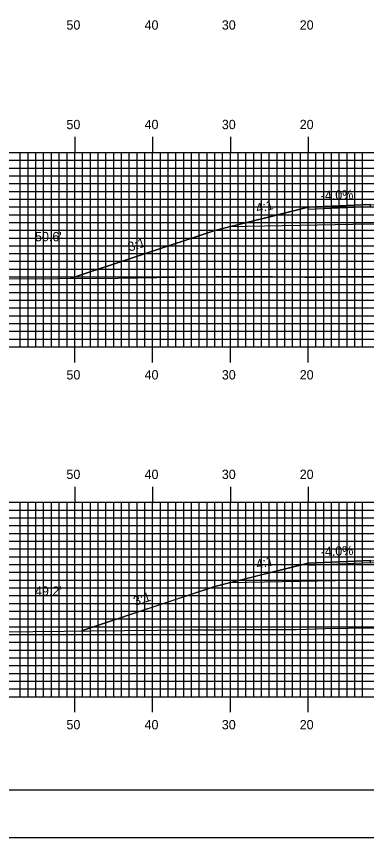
# Model space of a CAD drawing. Extents: x 1765333 to 1765676, y 442591 to 442811.
# Drawn here: x 1765440.9 to 1765485.9, y 442590.5 to 442696.2 of the extents above; entities that cross this region are included whole.
import ezdxf

# ---------------------------------------------------------------- set-up
doc = ezdxf.new("R2010")
doc.units = 0
for name, color, linetype in [('ANNOTATION', 7, 'Continuous'), ('BORDER', 7, 'Continuous'), ('D_Roadway_Centerline', 7, 'Continuous'), ('D_Roadway_Edge_Shoulder', 7, 'Continuous'), ('D_Roadway_SlopeLines', 7, 'Continuous'), ('D_Roadway_SubGrade', 7, 'Continuous'), ('D_Text_Standard', 7, 'Continuous'), ('H_V ANNOTATION', 7, 'Continuous'), ('MAJOR', 7, 'Continuous'), ('MINOR', 7, 'Continuous'), ('PLOT BOUNDARY', 7, 'Continuous'), ('S_Roadway_Centerline', 7, 'Continuous')]:
    doc.layers.add(name, color=color, linetype=linetype)

msp = doc.modelspace()

# ---------------------------------------------------------------- linework, layer by layer
at = {"layer": 'BORDER'}
msp.add_lwpolyline([(1765348.77, 442596.67), (1765668.77, 442596.67), (1765668.77, 442806.67), (1765348.77, 442806.67)], close=True, dxfattribs=at)
at = {"layer": 'D_Roadway_Centerline'}
for points in [[(1765447.79, 442662.46), (1765466.37, 442668.65), (1765466.37, 442668.65), (1765466.86, 442668.77), (1765468.2, 442669.11), (1765468.2, 442669.11), (1765473.59, 442670.45), (1765478.37, 442671.65), (1765478.37, 442671.65), (1765486.37, 442671.97), (1765486.38, 442671.97), (1765498.37, 442671.71), (1765510.37, 442671.44), (1765518.37, 442671.12), (1765518.37, 442671.12), (1765526.92, 442668.98), (1765528.55, 442668.58), (1765529.56, 442668.32), (1765530.37, 442668.12), (1765546.65, 442662.7), (1765546.65, 442662.7)], [(1765449.22, 442617.13), (1765449.22, 442617.13), (1765460.52, 442620.9), (1765466.36, 442622.84), (1765466.37, 442622.85), (1765466.37, 442622.85), (1765468.2, 442623.3), (1765468.2, 442623.3), (1765472.08, 442624.28), (1765478.37, 442625.85), (1765486.37, 442626.17), (1765497.05, 442625.98), (1765498.37, 442625.96), (1765510.36, 442625.72), (1765510.37, 442625.72), (1765518.36, 442625.4), (1765518.37, 442625.4), (1765528.54, 442622.85), (1765528.54, 442622.85), (1765528.96, 442622.75), (1765530.37, 442622.4), (1765535.39, 442620.72), (1765546.52, 442617.01)]]:
    msp.add_lwpolyline(points, dxfattribs=at)
at = {"layer": 'D_Roadway_Edge_Shoulder'}
for points in [[(1765486.37, 442671.97), (1765478.37, 442671.65), (1765478.37, 442671.4), (1765486.37, 442671.72)], [(1765486.37, 442626.17), (1765478.37, 442625.85), (1765478.37, 442625.6), (1765486.37, 442625.92)]]:
    msp.add_lwpolyline(points, close=True, dxfattribs=at)
at = {"layer": 'D_Roadway_SlopeLines'}
for points in [[(1765478.37, 442671.65), (1765466.37, 442668.65), (1765447.79, 442662.46)], [(1765478.37, 442625.85), (1765466.37, 442622.85), (1765449.22, 442617.13)]]:
    msp.add_lwpolyline(points, dxfattribs=at)
at = {"layer": 'D_Roadway_SubGrade'}
for points in [[(1765486.37, 442669.47), (1765468.2, 442669.11), (1765478.37, 442671.65), (1765478.37, 442671.4), (1765486.37, 442671.72), (1765498.37, 442671.46), (1765510.37, 442671.19), (1765518.37, 442670.87), (1765518.37, 442671.12), (1765528.55, 442668.58), (1765510.37, 442668.94), (1765498.37, 442669.21)], [(1765486.37, 442623.67), (1765468.2, 442623.3), (1765478.37, 442625.85), (1765478.37, 442625.6), (1765486.37, 442625.92), (1765498.37, 442625.71), (1765510.37, 442625.47), (1765518.37, 442625.15), (1765518.37, 442625.4), (1765528.54, 442622.85), (1765510.37, 442623.22), (1765498.37, 442623.46)]]:
    msp.add_lwpolyline(points, close=True, dxfattribs=at)
at = {"layer": 'MAJOR'}
for p, q in [((1765448.37, 442680.67), (1765448.37, 442678.67)), ((1765458.37, 442680.67), (1765458.37, 442678.67)), ((1765468.37, 442680.67), (1765468.37, 442678.67)), ((1765478.37, 442680.67), (1765478.37, 442678.67)), ((1765358.37, 442678.67), (1765638.37, 442678.67)), ((1765358.37, 442678.67), (1765638.37, 442678.67)), ((1765448.37, 442653.67), (1765448.37, 442678.67)), ((1765458.37, 442653.67), (1765458.37, 442678.67)), ((1765468.37, 442653.67), (1765468.37, 442678.67)), ((1765478.37, 442653.67), (1765478.37, 442678.67)), ((1765358.37, 442673.67), (1765638.37, 442673.67)), ((1765358.37, 442668.67), (1765638.37, 442668.67)), ((1765358.37, 442663.67), (1765638.37, 442663.67)), ((1765358.37, 442658.67), (1765638.37, 442658.67)), ((1765358.37, 442653.67), (1765638.37, 442653.67)), ((1765358.37, 442653.67), (1765638.37, 442653.67)), ((1765448.37, 442651.66), (1765448.37, 442653.67)), ((1765458.37, 442651.66), (1765458.37, 442653.67)), ((1765468.37, 442651.66), (1765468.37, 442653.67)), ((1765478.37, 442651.66), (1765478.37, 442653.67)), ((1765448.37, 442635.67), (1765448.37, 442633.67)), ((1765458.37, 442635.67), (1765458.37, 442633.67)), ((1765468.37, 442635.67), (1765468.37, 442633.67)), ((1765478.37, 442635.67), (1765478.37, 442633.67)), ((1765358.37, 442633.67), (1765638.37, 442633.67)), ((1765358.37, 442633.67), (1765638.37, 442633.67)), ((1765448.37, 442608.67), (1765448.37, 442633.67)), ((1765458.37, 442608.67), (1765458.37, 442633.67)), ((1765468.37, 442608.67), (1765468.37, 442633.67)), ((1765478.37, 442608.67), (1765478.37, 442633.67)), ((1765358.37, 442628.67), (1765638.37, 442628.67)), ((1765358.37, 442623.67), (1765638.37, 442623.67)), ((1765358.37, 442618.67), (1765638.37, 442618.67)), ((1765358.37, 442613.67), (1765638.37, 442613.67)), ((1765358.37, 442608.67), (1765638.37, 442608.67)), ((1765358.37, 442608.67), (1765638.37, 442608.67)), ((1765448.37, 442606.66), (1765448.37, 442608.67)), ((1765458.37, 442606.66), (1765458.37, 442608.67)), ((1765468.37, 442606.66), (1765468.37, 442608.67)), ((1765478.37, 442606.66), (1765478.37, 442608.67))]:
    msp.add_line(p, q, dxfattribs=at)
at = {"layer": 'MINOR'}
for p, q in [((1765441.37, 442653.67), (1765441.37, 442678.67)), ((1765442.37, 442653.67), (1765442.37, 442678.67)), ((1765443.37, 442653.67), (1765443.37, 442678.67)), ((1765444.37, 442653.67), (1765444.37, 442678.67)), ((1765445.37, 442653.67), (1765445.37, 442678.67)), ((1765446.37, 442653.67), (1765446.37, 442678.67)), ((1765447.37, 442653.67), (1765447.37, 442678.67)), ((1765449.37, 442653.67), (1765449.37, 442678.67)), ((1765450.37, 442653.67), (1765450.37, 442678.67)), ((1765451.37, 442653.67), (1765451.37, 442678.67)), ((1765452.37, 442653.67), (1765452.37, 442678.67)), ((1765453.37, 442653.67), (1765453.37, 442678.67)), ((1765454.37, 442653.67), (1765454.37, 442678.67)), ((1765455.37, 442653.67), (1765455.37, 442678.67)), ((1765456.37, 442653.67), (1765456.37, 442678.67)), ((1765457.37, 442653.67), (1765457.37, 442678.67)), ((1765459.37, 442653.67), (1765459.37, 442678.67)), ((1765460.37, 442653.67), (1765460.37, 442678.67)), ((1765461.37, 442653.67), (1765461.37, 442678.67)), ((1765462.37, 442653.67), (1765462.37, 442678.67)), ((1765463.37, 442653.67), (1765463.37, 442678.67)), ((1765464.37, 442653.67), (1765464.37, 442678.67)), ((1765465.37, 442653.67), (1765465.37, 442678.67)), ((1765466.37, 442653.67), (1765466.37, 442678.67)), ((1765467.37, 442653.67), (1765467.37, 442678.67)), ((1765469.37, 442653.67), (1765469.37, 442678.67)), ((1765470.37, 442653.67), (1765470.37, 442678.67)), ((1765471.37, 442653.67), (1765471.37, 442678.67)), ((1765472.37, 442653.67), (1765472.37, 442678.67)), ((1765473.37, 442653.67), (1765473.37, 442678.67)), ((1765474.37, 442653.67), (1765474.37, 442678.67)), ((1765475.37, 442653.67), (1765475.37, 442678.67)), ((1765476.37, 442653.67), (1765476.37, 442678.67)), ((1765477.37, 442653.67), (1765477.37, 442678.67)), ((1765479.37, 442653.67), (1765479.37, 442678.67)), ((1765480.37, 442653.67), (1765480.37, 442678.67)), ((1765481.37, 442653.67), (1765481.37, 442678.67)), ((1765482.37, 442653.67), (1765482.37, 442678.67)), ((1765483.37, 442653.67), (1765483.37, 442678.67)), ((1765484.37, 442653.67), (1765484.37, 442678.67)), ((1765485.37, 442653.67), (1765485.37, 442678.67)), ((1765358.37, 442677.67), (1765638.37, 442677.67)), ((1765358.37, 442676.67), (1765638.37, 442676.67)), ((1765358.37, 442675.67), (1765638.37, 442675.67)), ((1765358.37, 442674.67), (1765638.37, 442674.67)), ((1765358.37, 442672.67), (1765638.37, 442672.67)), ((1765358.37, 442671.67), (1765638.37, 442671.67)), ((1765358.37, 442670.67), (1765638.37, 442670.67)), ((1765358.37, 442669.67), (1765638.37, 442669.67)), ((1765358.37, 442667.67), (1765638.37, 442667.67)), ((1765358.37, 442666.67), (1765638.37, 442666.67)), ((1765358.37, 442665.67), (1765638.37, 442665.67)), ((1765358.37, 442664.67), (1765638.37, 442664.67)), ((1765358.37, 442662.67), (1765638.37, 442662.67)), ((1765358.37, 442661.67), (1765638.37, 442661.67)), ((1765358.37, 442660.67), (1765638.37, 442660.67)), ((1765358.37, 442659.67), (1765638.37, 442659.67)), ((1765358.37, 442657.67), (1765638.37, 442657.67)), ((1765358.37, 442656.67), (1765638.37, 442656.67)), ((1765358.37, 442655.67), (1765638.37, 442655.67)), ((1765358.37, 442654.67), (1765638.37, 442654.67)), ((1765441.37, 442608.67), (1765441.37, 442633.67)), ((1765442.37, 442608.67), (1765442.37, 442633.67)), ((1765443.37, 442608.67), (1765443.37, 442633.67)), ((1765444.37, 442608.67), (1765444.37, 442633.67)), ((1765445.37, 442608.67), (1765445.37, 442633.67)), ((1765446.37, 442608.67), (1765446.37, 442633.67)), ((1765447.37, 442608.67), (1765447.37, 442633.67)), ((1765449.37, 442608.67), (1765449.37, 442633.67)), ((1765450.37, 442608.67), (1765450.37, 442633.67)), ((1765451.37, 442608.67), (1765451.37, 442633.67)), ((1765452.37, 442608.67), (1765452.37, 442633.67)), ((1765453.37, 442608.67), (1765453.37, 442633.67)), ((1765454.37, 442608.67), (1765454.37, 442633.67)), ((1765455.37, 442608.67), (1765455.37, 442633.67)), ((1765456.37, 442608.67), (1765456.37, 442633.67)), ((1765457.37, 442608.67), (1765457.37, 442633.67)), ((1765459.37, 442608.67), (1765459.37, 442633.67)), ((1765460.37, 442608.67), (1765460.37, 442633.67)), ((1765461.37, 442608.67), (1765461.37, 442633.67)), ((1765462.37, 442608.67), (1765462.37, 442633.67)), ((1765463.37, 442608.67), (1765463.37, 442633.67)), ((1765464.37, 442608.67), (1765464.37, 442633.67)), ((1765465.37, 442608.67), (1765465.37, 442633.67)), ((1765466.37, 442608.67), (1765466.37, 442633.67)), ((1765467.37, 442608.67), (1765467.37, 442633.67)), ((1765469.37, 442608.67), (1765469.37, 442633.67)), ((1765470.37, 442608.67), (1765470.37, 442633.67)), ((1765471.37, 442608.67), (1765471.37, 442633.67)), ((1765472.37, 442608.67), (1765472.37, 442633.67)), ((1765473.37, 442608.67), (1765473.37, 442633.67)), ((1765474.37, 442608.67), (1765474.37, 442633.67)), ((1765475.37, 442608.67), (1765475.37, 442633.67)), ((1765476.37, 442608.67), (1765476.37, 442633.67)), ((1765477.37, 442608.67), (1765477.37, 442633.67)), ((1765479.37, 442608.67), (1765479.37, 442633.67)), ((1765480.37, 442608.67), (1765480.37, 442633.67)), ((1765481.37, 442608.67), (1765481.37, 442633.67)), ((1765482.37, 442608.67), (1765482.37, 442633.67)), ((1765483.37, 442608.67), (1765483.37, 442633.67)), ((1765484.37, 442608.67), (1765484.37, 442633.67)), ((1765485.37, 442608.67), (1765485.37, 442633.67)), ((1765358.37, 442632.67), (1765638.37, 442632.67)), ((1765358.37, 442631.67), (1765638.37, 442631.67)), ((1765358.37, 442630.67), (1765638.37, 442630.67)), ((1765358.37, 442629.67), (1765638.37, 442629.67)), ((1765358.37, 442627.67), (1765638.37, 442627.67)), ((1765358.37, 442626.67), (1765638.37, 442626.67)), ((1765358.37, 442625.67), (1765638.37, 442625.67)), ((1765358.37, 442624.67), (1765638.37, 442624.67)), ((1765358.37, 442622.67), (1765638.37, 442622.67)), ((1765358.37, 442621.67), (1765638.37, 442621.67)), ((1765358.37, 442620.67), (1765638.37, 442620.67)), ((1765358.37, 442619.67), (1765638.37, 442619.67)), ((1765358.37, 442617.67), (1765638.37, 442617.67)), ((1765358.37, 442616.67), (1765638.37, 442616.67)), ((1765358.37, 442615.67), (1765638.37, 442615.67)), ((1765358.37, 442614.67), (1765638.37, 442614.67)), ((1765358.37, 442612.67), (1765638.37, 442612.67)), ((1765358.37, 442611.67), (1765638.37, 442611.67)), ((1765358.37, 442610.67), (1765638.37, 442610.67)), ((1765358.37, 442609.67), (1765638.37, 442609.67))]:
    msp.add_line(p, q, dxfattribs=at)
at = {"layer": 'PLOT BOUNDARY'}
msp.add_lwpolyline([(1765332.58, 442590.55), (1765672.58, 442590.55), (1765672.58, 442810.55), (1765332.58, 442810.55)], close=True, dxfattribs=at)
at = {"layer": 'S_Roadway_Centerline'}
for points in [[(1765431.28, 442662.36), (1765446.18, 442662.44), (1765453.89, 442662.51), (1765463.96, 442662.67), (1765466.53, 442662.72), (1765471.86, 442662.77), (1765475.74, 442662.69), (1765480.11, 442662.61), (1765480.14, 442662.69), (1765482.24, 442662.72), (1765491.42, 442662.81), (1765500.11, 442662.88), (1765512.06, 442662.84), (1765516.08, 442662.8), (1765517.93, 442662.79), (1765529.11, 442662.71), (1765535.88, 442662.67), (1765552.97, 442662.71)], [(1765439, 442617.02), (1765447.02, 442617.11), (1765450.46, 442617.14), (1765463.23, 442617.26), (1765466.88, 442617.28), (1765467.84, 442617.25), (1765469.61, 442617.31), (1765474.73, 442617.31), (1765476.73, 442617.31), (1765476.84, 442617.32), (1765480.58, 442617.43), (1765486.46, 442617.52), (1765496.94, 442617.5), (1765504.18, 442617.48), (1765520.59, 442617.3), (1765522.1, 442617.31), (1765534.42, 442617.26), (1765540.25, 442617.13), (1765554.75, 442616.85)]]:
    msp.add_lwpolyline(points, dxfattribs=at)

# ---------------------------------------------------------------- texts
at = {"layer": 'ANNOTATION'}
for s, rotation, p in [('-4.0%', 2.2906, (1765480, 442672.52)), ('4:1', 14.0385, (1765471.82, 442670.87)), ('3:1', 18.437, (1765455.42, 442665.91)), ('-4.0%', 2.2908, (1765480, 442626.72)), ('4:1', 14.0389, (1765471.82, 442625.07)), ('3:1', 18.4344, (1765456.13, 442620.34))]:
    msp.add_text(s, height=1.2, rotation=rotation, dxfattribs=at).set_placement(p)
at = {"layer": 'D_Text_Standard'}
for s, p in [("50.6'", (1765443.26, 442667.25)), ("49.2'", (1765443.26, 442621.66))]:
    msp.add_text(s, height=1.2, dxfattribs=at).set_placement(p)
at = {"layer": 'H_V ANNOTATION'}
for s, p in [('50', (1765447.3, 442694.47)), ('40', (1765457.34, 442694.47)), ('30', (1765467.27, 442694.47)), ('20', (1765477.28, 442694.47)), ('50', (1765447.3, 442681.67)), ('40', (1765457.34, 442681.67)), ('30', (1765467.27, 442681.67)), ('20', (1765477.28, 442681.67)), ('50', (1765447.3, 442649.47)), ('40', (1765457.34, 442649.47)), ('30', (1765467.27, 442649.47)), ('20', (1765477.28, 442649.47)), ('50', (1765447.3, 442636.67)), ('40', (1765457.34, 442636.67)), ('30', (1765467.27, 442636.67)), ('20', (1765477.28, 442636.67)), ('50', (1765447.3, 442604.47)), ('40', (1765457.34, 442604.47)), ('30', (1765467.27, 442604.47)), ('20', (1765477.28, 442604.47))]:
    msp.add_text(s, height=1.2, dxfattribs=at).set_placement(p)

doc.saveas('drawing.dxf')
